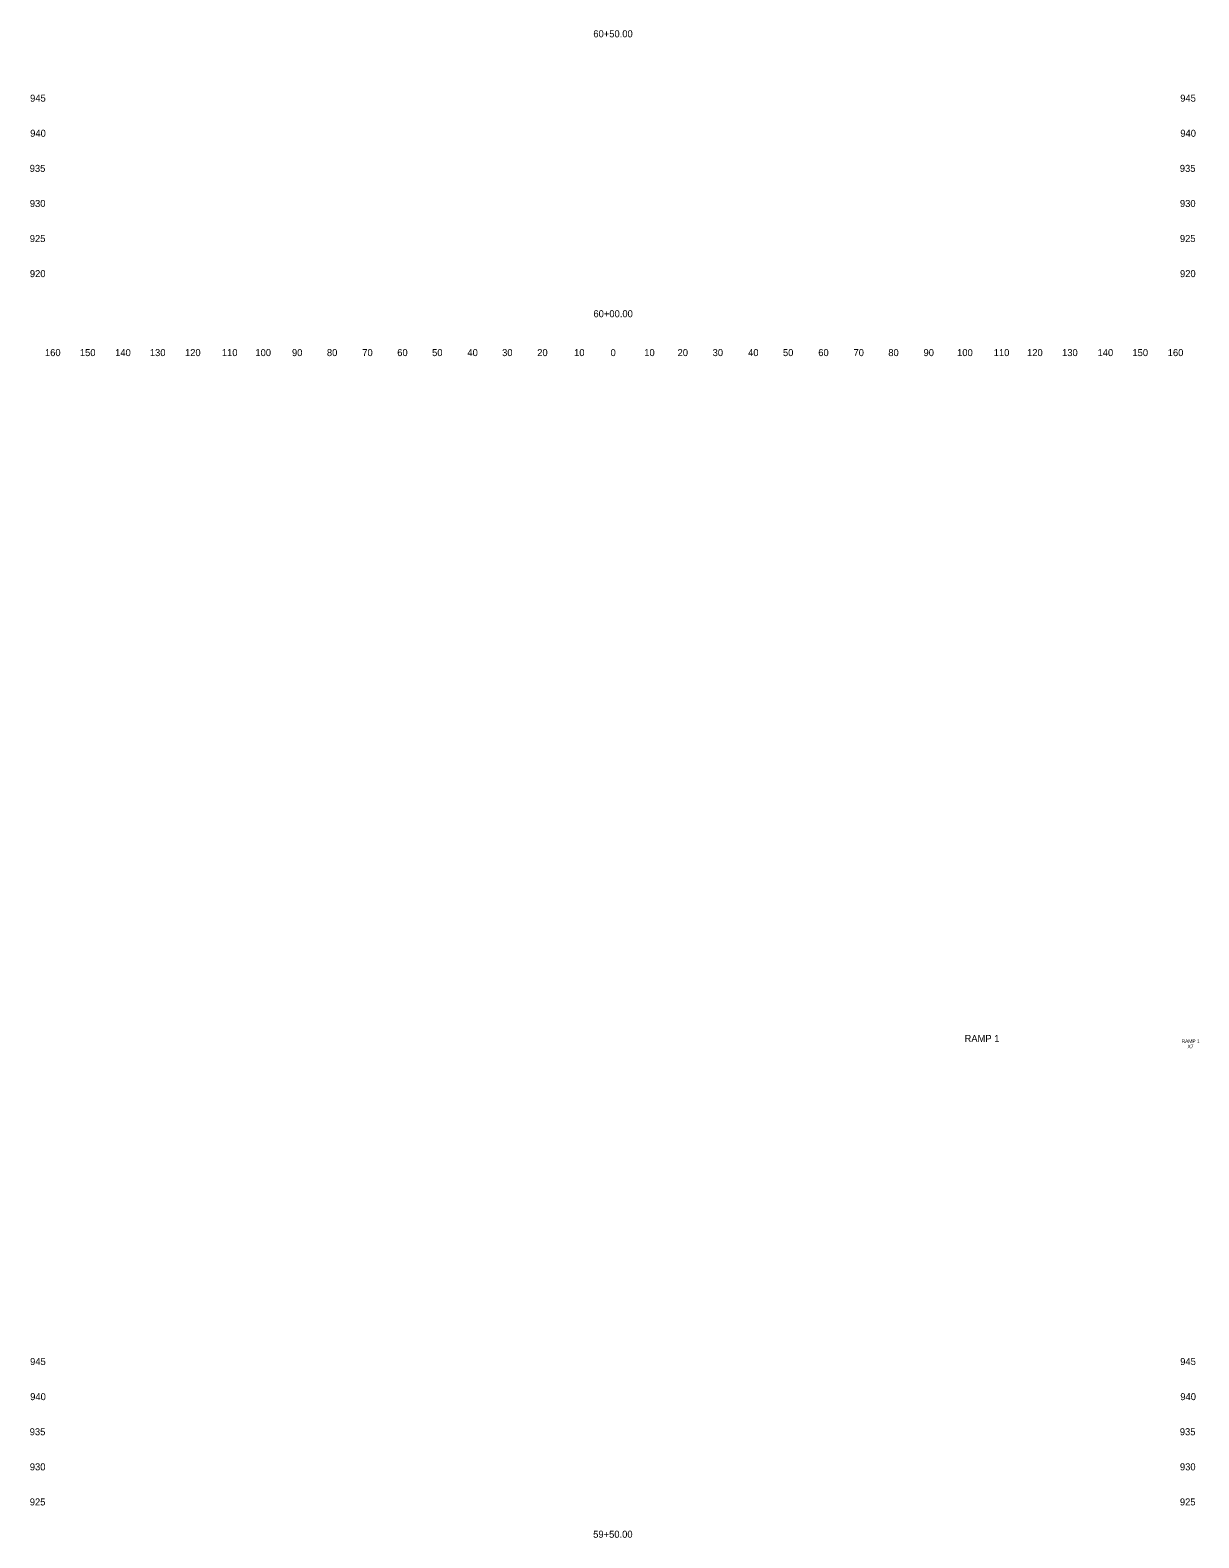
# Model space of a CAD drawing. Extents: x 4994 to 7869, y 4997 to 8804.
# Drawn here: x 4993.9 to 5327, y 7460.8 to 7890.4 of the extents above; entities that cross this region are included whole.
import ezdxf

# ---------------------------------------------------------------- set-up
doc = ezdxf.new("R2010")
doc.units = 0
for name, color, linetype in [('RD_SHT_ID', 7, 'Continuous'), ('RD_XS_TX_Offset', 7, 'Continuous'), ('RD_XS_TX_Station', 7, 'Continuous')]:
    doc.layers.add(name, color=color, linetype=linetype)

msp = doc.modelspace()

# ---------------------------------------------------------------- texts
at = {"layer": 'RD_SHT_ID'}
for s, height, p in [('RAMP 1', 2, (5260.19, 7602.06)), ('RAMP 1', 1, (5322.06, 7601.8)), ('X7', 1, (5323.74, 7600.3))]:
    msp.add_text(s, height=height, dxfattribs=at).set_placement(p)
at = {"layer": 'RD_XS_TX_Offset'}
for s, p in [('945', (4993.86, 7870)), ('945', (5321.66, 7870)), ('940', (4993.89, 7860)), ('940', (5321.69, 7860)), ('935', (4993.75, 7850)), ('935', (5321.55, 7850)), ('930', (4993.78, 7840)), ('930', (5321.58, 7840)), ('925', (4993.77, 7830)), ('925', (5321.57, 7830)), ('920', (4993.8, 7820)), ('920', (5321.6, 7820)), ('160', (4998.1, 7797.5)), ('150', (5008.04, 7797.5)), ('140', (5018.1, 7797.5)), ('130', (5027.99, 7797.5)), ('120', (5038.01, 7797.5)), ('110', (5048.51, 7797.5)), ('100', (5058.07, 7797.5)), ('90', (5068.5, 7797.5)), ('80', (5078.46, 7797.5)), ('70', (5088.54, 7797.5)), ('60', (5098.5, 7797.5)), ('50', (5108.43, 7797.5)), ('40', (5118.5, 7797.5)), ('30', (5128.39, 7797.5)), ('20', (5138.4, 7797.5)), ('10', (5148.91, 7797.5)), ('0', (5159.3, 7797.5)), ('0', (5159.3, 7797.5)), ('10', (5168.91, 7797.5)), ('20', (5178.4, 7797.5)), ('30', (5188.39, 7797.5)), ('40', (5198.5, 7797.5)), ('50', (5208.43, 7797.5)), ('60', (5218.5, 7797.5)), ('70', (5228.54, 7797.5)), ('80', (5238.46, 7797.5)), ('90', (5248.5, 7797.5)), ('100', (5258.07, 7797.5)), ('110', (5268.51, 7797.5)), ('120', (5278.01, 7797.5)), ('130', (5287.99, 7797.5)), ('140', (5298.1, 7797.5)), ('150', (5308.04, 7797.5)), ('160', (5318.1, 7797.5)), ('945', (4993.86, 7510)), ('945', (5321.66, 7510)), ('940', (4993.89, 7500)), ('940', (5321.69, 7500)), ('935', (4993.75, 7490)), ('935', (5321.55, 7490)), ('930', (4993.78, 7480)), ('930', (5321.58, 7480)), ('925', (4993.77, 7470)), ('925', (5321.57, 7470))]:
    msp.add_text(s, height=2, dxfattribs=at).set_placement(p)
at = {"layer": 'RD_XS_TX_Station'}
for s, p in [('60+50.00', (5154.39, 7888.35)), ('60+00.00', (5154.42, 7808.58)), ('59+50.00', (5154.35, 7460.79))]:
    msp.add_text(s, height=2, dxfattribs=at).set_placement(p)

doc.saveas('drawing.dxf')
